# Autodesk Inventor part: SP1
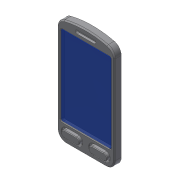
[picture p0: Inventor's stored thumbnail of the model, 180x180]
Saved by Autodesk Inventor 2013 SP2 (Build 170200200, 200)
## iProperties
Created: 2013-06
Part Number: SP1
Material: 一般
Document SubType Name: Modeling
Designer: 3214325
Density: 1 g/cm^3
Author: 3214325
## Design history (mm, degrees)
sketch "Sketch1"
  geometry: L1 (0, 95)-(25, 95); L2 (25, 90.993)-(25, 0); L3 (25, 0)-(-25, 0); L4 (-25, 0)-(-25, 90.993); L5 (-35, 0)-(35, 0) reference; L6 (0, -19)-(0, 114) reference; L7 (25, 93.419)-(25, 95); L8 (-25, 90.993)-(-25, 95); L9 (-25, 95)-(0, 95); A1 r 80 centre (0, 15) between (25, 90.993) and (-25, 90.993); 1 further point
  constraints: 14 end point, 4 parallel, 3 point on circle, 1 centre point, 1 collinear, 1 horizontal, 1 horizontal alignment, 1 perpendicular, 1 point on line, 1 tangent, 1 other
  dimensions: "d0" = 50 distance of L2.end L3.end; "d1" = 95 distance of L1.end L2.end; "d102" = 80 radius of A1
extrude "Extrusion1" new body sketch "Sketch1" distance "d2" = 9; taper "d3" = 0 deg
fillet "Fillet3" dims "d6" = 8
fillet "Fillet4" dims "d7" = 8
sketch "Sketch2"
  geometry: L1 (-22, 85)-(22, 85); L2 (22, 85)-(22, 15); L3 (22, 15)-(-22, 15); L4 (-22, 15)-(-22, 85); L5 (0, -19)-(0, 114) reference; L6 (-17, 0)-(17, 0) reference; A1 r 80 centre (0, 15) between (25, 90.993) and (-25, 90.993) reference; 2 further points
  constraints: 8 end point, 2 parallel, 1 horizontal, 1 perpendicular, 1 point on circle, 1 other
  dimensions: "d8" = 44 distance of L2.end L3.end; "d9" = 70 distance of L1.end L2.end; "d99" = 15 distance between parallel lines of L6 L3
extrude "Extrusion2" cut sketch "Sketch2" distance "d11" = 3.5; taper "d12" = 0 deg
fillet "Fillet5" dims "d13" = 1.5
fillet "Fillet6" dims "d14" = 1.5
fillet "Fillet7" dims "d15" = 1.5
fillet "Fillet8" dims "d16" = 1.5
sketch "Sketch3"
  geometry: L1 (-17, 0)-(17, 0) reference; L2 (-20, 11)-(-4, 11); L3 (-4, 11)-(-4, 5); L4 (-4, 5)-(-20, 5); L5 (-20, 5)-(-20, 11); L6 (4, 11)-(20, 11); L7 (20, 11)-(20, 5); L8 (20, 5)-(4, 5); L9 (4, 5)-(4, 11); L10 (0, -19)-(0, 114) reference; L11 (-3, 12)-(-21, 12); L12 (-21, 12)-(-21, 4); L13 (-21, 4)-(-3, 4); L14 (-3, 4)-(-3, 12); L15 (21, 12)-(3, 12); L16 (3, 12)-(3, 4); L17 (3, 4)-(21, 4); L18 (21, 4)-(21, 12); 1 further point
  constraints: 32 end point, 8 parallel, 4 perpendicular, 2 horizontal, 1 collinear, 8 other
  dimensions: "d17" = 6 distance of L2.end L3.end; "d18" = 6 distance of L6.end L7.end; "d19" = 8 distance between parallel lines of L9 L3; "d20" = 40 distance between parallel lines of L7 L5; "d21" = 11 distance between parallel lines of L2 L1; "d22" = 1 distance between parallel lines of L6 L15 (= d23); "d23" = 1 distance between parallel lines of L11 L2
extrude "Extrusion3" cut sketch "Sketch3" distance "d24" = 2; taper "d25" = 0 deg
fillet "Fillet22"
fillet "Fillet23"
fillet "Fillet24"
fillet "Fillet25"
sketch "Sketch4"
  geometry: L1 (-7, 4)-(-17, 4) reference; L2 (-17, 12)-(-7, 12) reference; L3 (7, 12)-(17, 12) reference; L4 (17, 4)-(7, 4) reference; L5 (-7, 5)-(-17, 5); L6 (-17, 11)-(-7, 11); L7 (17, 5)-(7, 5); L8 (7, 11)-(17, 11); A1 r 4 centre (-17, 8) between (-17, 12) and (-17, 4) reference; A2 r 4 centre (-7, 8) between (-7, 4) and (-7, 12) reference; A3 r 4 centre (17, 8) between (17, 4) and (17, 12) reference; A4 r 4 centre (7, 8) between (7, 12) and (7, 4) reference; A5 r 3 centre (-7, 8) between (-7, 5) and (-7, 11); A6 r 3 centre (-17, 8) between (-17, 11) and (-17, 5); A7 r 3 centre (17, 8) between (17, 5) and (17, 11); A8 r 3 centre (7, 8) between (7, 11) and (7, 5)
  constraints: 8 end point, 8 point on circle, 4 centre point, 6 other
  dimensions: "d100" = 1 distance between parallel lines of L2 L6; "d101" = 1 distance between parallel lines of L8 L3 (= d100)
extrude "Extrusion4" join sketch "Sketch4" distance "d35" = 3.5; taper "d36" = 0 deg
fillet "Fillet17" dims "d40" = 0.5
chamfer "Chamfer2" distance "d47" = 0.5; stored, may be unused: second distance "d48" = 2, angle "d49" = 45 deg
chamfer "Chamfer3" distance "d50" = 0.5; stored, may be unused: second distance "d51" = 2, angle "d52" = 45 deg
sketch "Sketch7"
  geometry: L1 (20.5, 15)-(-20.5, 15) reference; L2 (22, 83.5)-(22, 16.5) reference; L3 (-20.5, 85)-(20.5, 85) reference; L4 (-22, 16.5)-(-22, 83.5) reference; A1 r 1.5 centre (-20.5, 16.5) between (-22, 16.5) and (-20.5, 15) reference; A2 r 1.5 centre (20.5, 16.5) between (20.5, 15) and (22, 16.5) reference; A3 r 1.5 centre (20.5, 83.5) between (22, 83.5) and (20.5, 85) reference; A4 r 1.5 centre (-20.5, 83.5) between (-20.5, 85) and (-22, 83.5) reference; 1 further point
extrude "Extrusion7" new body sketch "Sketch7" distance "d59" = 3; taper "d60" = 0 deg
chamfer "Chamfer6" distance "d61" = 0.5; stored, may be unused: second distance "d62" = 2, angle "d63" = 45 deg
fillet "Fillet20" dims "d77" = 8
chamfer "Chamfer8" distance "d78" = 1; stored, may be unused: second distance "d79" = 2, angle "d80" = 45 deg
workplane "Work Plane1"
sketch "Sketch10"
  geometry: L1 (20.5, 85.5)-(-20.5, 85.5) reference; L2 (0, 85.5)-(0, 94); L3 (-7.5, 91)-(7.5, 91); L4 (7.5, 88)-(-7.5, 88); L5 (-20.5, 85)-(20.5, 85) reference; A1 r 79 centre (0, 15) between (18.653, 91.766) and (-18.653, 91.766) reference; A2 r 1.5 centre (-7.5, 89.5) between (-7.5, 91) and (-7.5, 88); A3 r 1.5 centre (7.5, 89.5) between (7.5, 88) and (7.5, 91); 3 further points
  constraints: 6 end point, 5 point on circle, 4 tangent, 3 midpoint, 2 centre point, 1 equal radius, 1 vertical alignment
  dimensions: "d81" = 15 distance of A3.centre A2.centre; "d83" = 3 diameter of A3; "d103" = 3 distance between parallel lines of L4 L5
extrude "Extrusion10" cut sketch "Sketch10" distance "d85" = 2; taper "d86" = 0 deg
sketch "Sketch13"
  geometry: L1 (-25, 8)-(-25, 84.964) reference; L2 (17, 0)-(-17, 0) reference; L3 (25, 84.964)-(25, 8) reference; A1 r 8 centre (17, 84.964) between (25, 84.964) and (18.889, 92.738) reference; A2 r 80 centre (0, 15) between (18.889, 92.738) and (-18.889, 92.738) reference; A3 r 8 centre (-17, 84.964) between (-18.889, 92.738) and (-25, 84.964) reference; A4 r 8 centre (-17, 8) between (-25, 8) and (-17, 0) reference; A5 r 8 centre (17, 8) between (17, 0) and (25, 8) reference; 1 further point
sketch "Sketch12"
  geometry: L1 (95, 0)-(95, 8) reference; L2 (95, 0)-(92.738, 0) reference; L3 (95, 3)-(95, 0); L4 (95, 0)-(87.859, 0); A1 r 10 centre (87.859, 10) between (87.859, 0) and (95, 3); 1 further point
  constraints: 4 end point, 2 perpendicular, 2 point on circle, 2 point on line, 2 tangent, 1 centre point
  dimensions: "d89" = 3 distance from line of L2 L3.start; "d90" = 10 radius of A1
sweep "Sweep1" sketch "Sketch13", "Sketch12" dims "d91" = 0
chamfer "Chamfer9" distance "d93" = 0.5; stored, may be unused: second distance "d94" = 2, angle "d95" = 45 deg
body "Solid1"
body "Solid3"
node "Projected Loop1"
node "Projected Loop2"
